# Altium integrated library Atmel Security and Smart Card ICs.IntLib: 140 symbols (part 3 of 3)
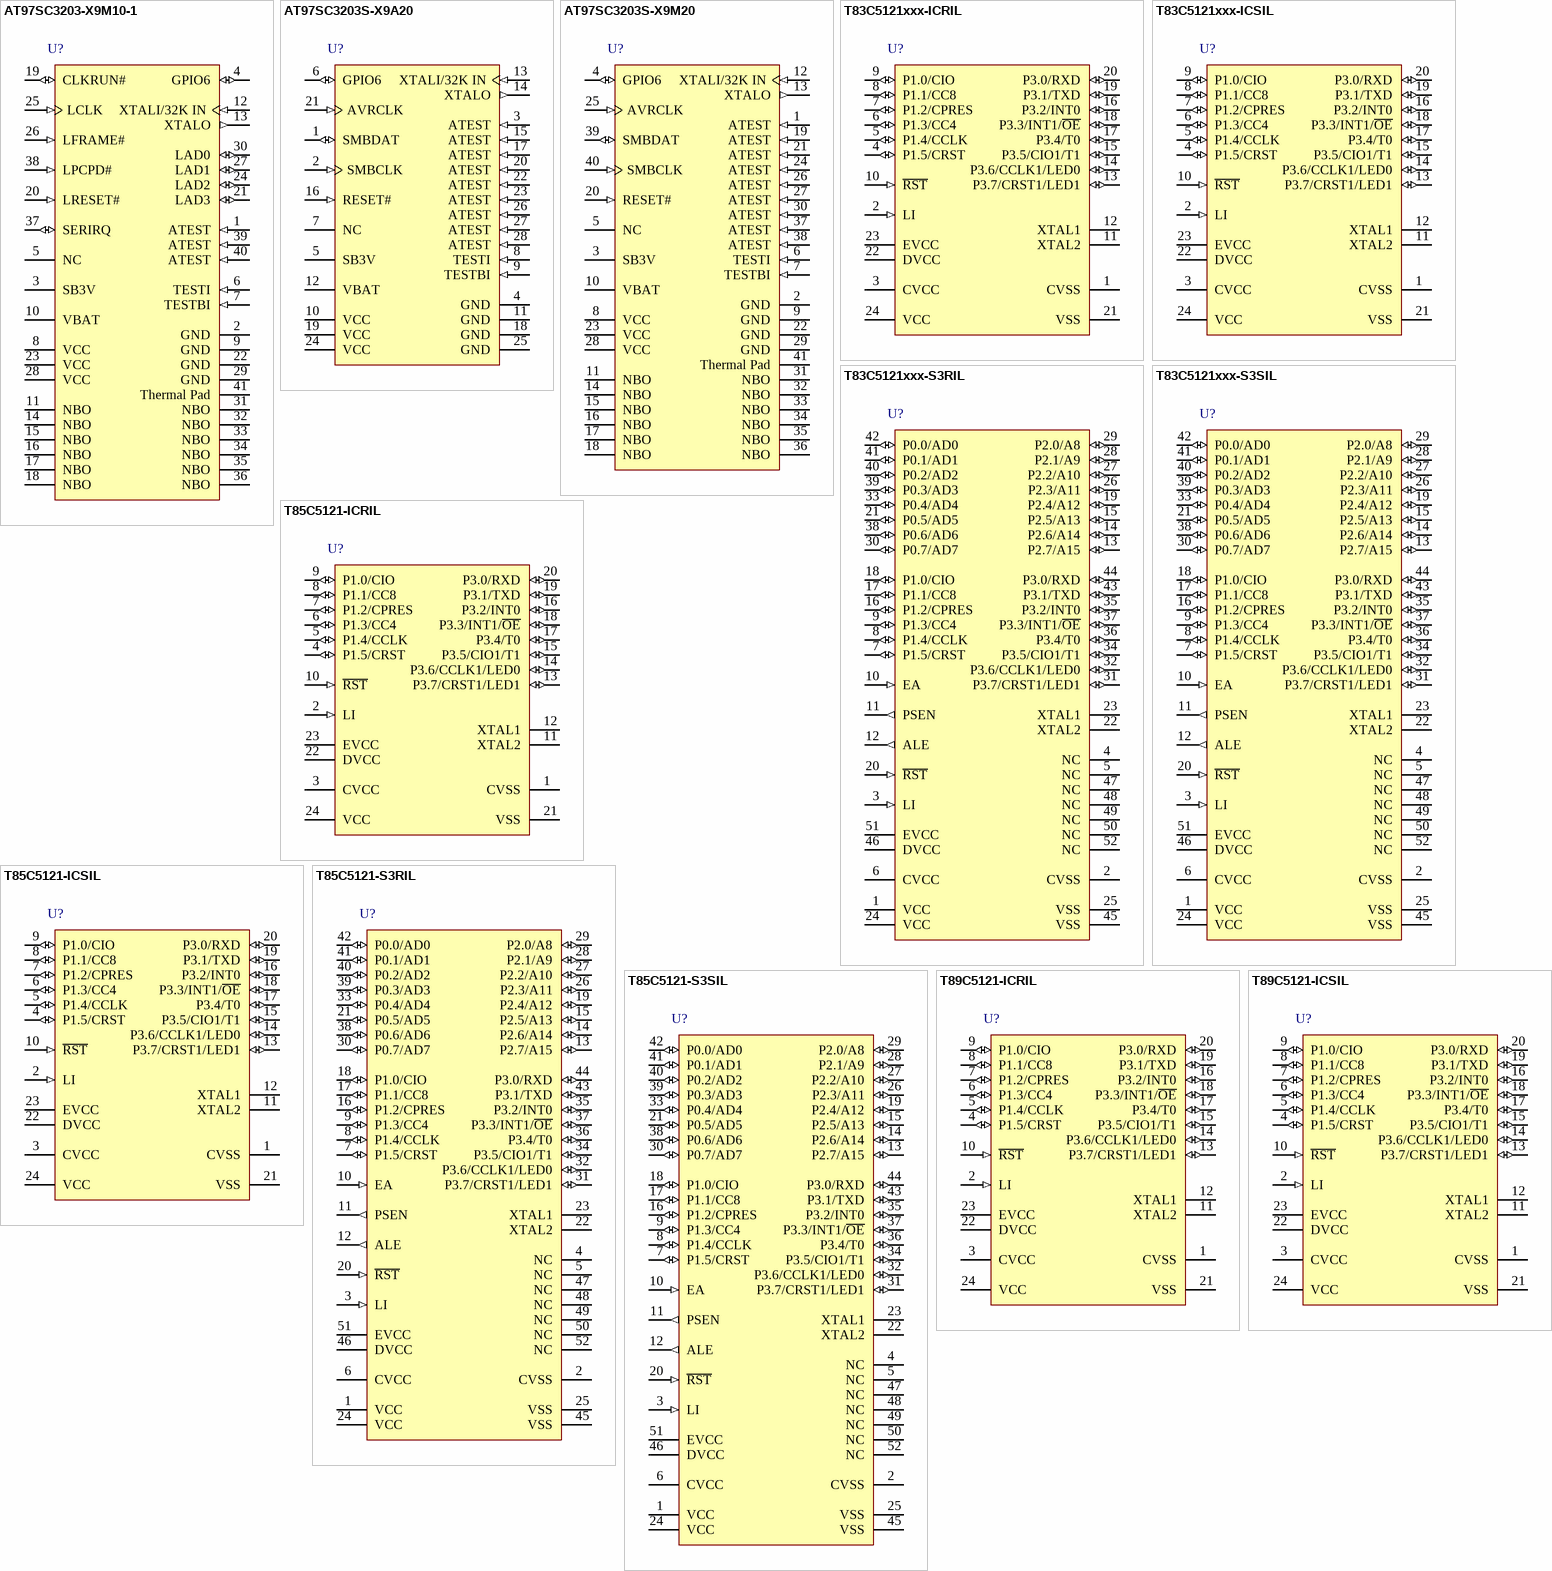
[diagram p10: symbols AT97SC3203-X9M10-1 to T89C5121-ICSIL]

## AT97SC3203S-X9A20
designator U?
Trusted Platform Module, SMBus Two-Wire Interface, Commercial (0 to 70 deg C), 28-Pin TSSOP, Pb-Free
footprint 28A3_N (TSOP, 28-Leads, Body 9.7x6.1mm, Pitch 0.65mm, IPC Medium Density)
footprint 28A3_L (TSOP, 28-Leads, Body 9.7x6.1mm, Pitch 0.65mm, IPC High Density)
footprint 28A3_M (TSOP, 28-Leads, Body 9.7x6.1mm, Pitch 0.65mm, IPC Low Density)
pins: 1 SMBDAT (io), 2 SMBCLK (in), 3 ATEST (in), 4 GND (power), 5 SB3V (power), 6 GPIO6 (io), 7 NC, 8 TESTI (in), 9 TESTBI (in), 10 VCC (power), 11 GND (power), 12 VBAT (power), 13 XTALI/32K IN (in), 14 XTALO (out), 15 ATEST (in), 16 RESET# (in), 17 ATEST (in), 18 GND (power), 19 VCC (power), 20 ATEST (in), 21 AVRCLK (in), 22 ATEST (in), 23 ATEST (in), 24 VCC (power), 25 GND (power), 26 ATEST (in), 27 ATEST (in), 28 ATEST (in)

## AT97SC3203S-X9M20
designator U?
Trusted Platform Module, SMBus Two-Wire Interface, Commercial (0 to 70 deg C), 40-Pin QFN, Pb-Free
footprint 40ML1_N (QFN, 40-Leads, Body 6x6mm, Pitch 0.5mm, IPC Medium Density)
footprint 40ML1_L (QFN, 40-Leads, Body 6x6mm, Pitch 0.5mm, IPC High Density)
footprint 40ML1_M (QFN, 40-Leads, Body 6x6mm, Pitch 0.5mm, IPC Low Density)
pins: 1 ATEST (in), 2 GND (power), 3 SB3V (power), 4 GPIO6 (io), 5 NC, 6 TESTI (in), 7 TESTBI (in), 8 VCC (power), 9 GND (power), 10 VBAT (power), 11 NBO, 12 XTALI/32K IN (in), 13 XTALO (out), 14 NBO, 15 NBO, 16 NBO, 17 NBO, 18 NBO, 19 ATEST (in), 20 RESET# (in), 21 ATEST (in), 22 GND (power), 23 VCC (power), 24 ATEST (in), 25 AVRCLK (in), 26 ATEST (in), 27 ATEST (in), 28 VCC (power), 29 GND (power), 30 ATEST (in), 31 NBO, 32 NBO, 33 NBO, 34 NBO, 35 NBO, 36 NBO, 37 ATEST (in), 38 ATEST (in), 39 SMBDAT (io), 40 SMBCLK (in), 41 Thermal Pad (power)

## T83C5121xxx-ICRIL
designator U?
8-bit Microcontroller with Multiprotocol Smart Card Interface, Industrial, 24-Pin SOIC Pkg, Tape and Reel
footprint SSOP24_N (SOP, 24-Leads, Body 8.2x5.3mm, Pitch 0.65mm, IPC Medium Density)
footprint SSOP24_L (SOP, 24-Leads, Body 8.2x5.3mm, Pitch 0.65mm, IPC High Density)
footprint SSOP24_M (SOP, 24-Leads, Body 8.2x5.3mm, Pitch 0.65mm, IPC Low Density)
pins: 1 CVSS (power), 2 LI (in), 3 CVCC (power), 4 P1.5/CRST (io), 5 P1.4/CCLK (io), 6 P1.3/CC4 (io), 7 P1.2/CPRES (io), 8 P1.1/CC8 (io), 9 P1.0/CIO (io), 10 ~{RST} (in), 11 XTAL2, 12 XTAL1, 13 P3.7/CRST1/LED1 (io), 14 P3.6/CCLK1/LED0 (io), 15 P3.5/CIO1/T1 (io), 16 P3.2/INT0 (io), 17 P3.4/T0 (io), 18 P3.3/INT1/~{OE} (io), 19 P3.1/TXD (io), 20 P3.0/RXD (io), 21 VSS (power), 22 DVCC (power), 23 EVCC (power), 24 VCC (power)

## T83C5121xxx-ICSIL
designator U?
8-bit Microcontroller with Multiprotocol Smart Card Interface, Industrial, 24-Pin SOIC Pkg, Stick
footprint SSOP24_N (SOP, 24-Leads, Body 8.2x5.3mm, Pitch 0.65mm, IPC Medium Density)
footprint SSOP24_L (SOP, 24-Leads, Body 8.2x5.3mm, Pitch 0.65mm, IPC High Density)
footprint SSOP24_M (SOP, 24-Leads, Body 8.2x5.3mm, Pitch 0.65mm, IPC Low Density)
pins: 1 CVSS (power), 2 LI (in), 3 CVCC (power), 4 P1.5/CRST (io), 5 P1.4/CCLK (io), 6 P1.3/CC4 (io), 7 P1.2/CPRES (io), 8 P1.1/CC8 (io), 9 P1.0/CIO (io), 10 ~{RST} (in), 11 XTAL2, 12 XTAL1, 13 P3.7/CRST1/LED1 (io), 14 P3.6/CCLK1/LED0 (io), 15 P3.5/CIO1/T1 (io), 16 P3.2/INT0 (io), 17 P3.4/T0 (io), 18 P3.3/INT1/~{OE} (io), 19 P3.1/TXD (io), 20 P3.0/RXD (io), 21 VSS (power), 22 DVCC (power), 23 EVCC (power), 24 VCC (power)

## T83C5121xxx-S3RIL
designator U?
8-bit Microcontroller with Multiprotocol Smart Card Interface, Industrial, 52-Pin LCC Pkg, Tape and Reel; Note: Contact Atmel for availability
footprint PLCC52_N (Leaded Chip Carrier, 52-Leads, Body 19x19mm, Pitch 1.27mm, IPC Medium Density)
footprint PLCC52_L (Leaded Chip Carrier, 52-Leads, Body 19x19mm, Pitch 1.27mm, IPC High Density)
footprint PLCC52_M (Leaded Chip Carrier, 52-Leads, Body 19x19mm, Pitch 1.27mm, IPC Low Density)
pins: 1 VCC (power), 2 CVSS (power), 3 LI (in), 4 NC, 5 NC, 6 CVCC (power), 7 P1.5/CRST (io), 8 P1.4/CCLK (io), 9 P1.3/CC4 (io), 10 EA (in), 11 PSEN (out), 12 ALE (out), 13 P2.7/A15 (io), 14 P2.6/A14 (io), 15 P2.5/A13 (io), 16 P1.2/CPRES (io), 17 P1.1/CC8 (io), 18 P1.0/CIO (io), 19 P2.4/A12 (io), 20 ~{RST} (in), 21 P0.5/AD5 (io), 22 XTAL2, 23 XTAL1, 24 VCC (power), 25 VSS (power), 26 P2.3/A11 (io), 27 P2.2/A10 (io), 28 P2.1/A9 (io), 29 P2.0/A8 (io), 30 P0.7/AD7 (io), 31 P3.7/CRST1/LED1 (io), 32 P3.6/CCLK1/LED0 (io), 33 P0.4/AD4 (io), 34 P3.5/CIO1/T1 (io), 35 P3.2/INT0 (io), 36 P3.4/T0 (io), 37 P3.3/INT1/~{OE} (io), 38 P0.6/AD6 (io), 39 P0.3/AD3 (io), 40 P0.2/AD2 (io), 41 P0.1/AD1 (io), 42 P0.0/AD0 (io), 43 P3.1/TXD (io), 44 P3.0/RXD (io), 45 VSS (power), 46 DVCC (power), 47 NC, 48 NC, 49 NC, 50 NC, 51 EVCC (power), 52 NC

## T83C5121xxx-S3SIL
designator U?
8-bit Microcontroller with Multiprotocol Smart Card Interface, Industrial, 52-Pin LCC Pkg, Stick; Note: Contact Atmel for availability
footprint PLCC52_N (Leaded Chip Carrier, 52-Leads, Body 19x19mm, Pitch 1.27mm, IPC Medium Density)
footprint PLCC52_L (Leaded Chip Carrier, 52-Leads, Body 19x19mm, Pitch 1.27mm, IPC High Density)
footprint PLCC52_M (Leaded Chip Carrier, 52-Leads, Body 19x19mm, Pitch 1.27mm, IPC Low Density)
pins: 1 VCC (power), 2 CVSS (power), 3 LI (in), 4 NC, 5 NC, 6 CVCC (power), 7 P1.5/CRST (io), 8 P1.4/CCLK (io), 9 P1.3/CC4 (io), 10 EA (in), 11 PSEN (out), 12 ALE (out), 13 P2.7/A15 (io), 14 P2.6/A14 (io), 15 P2.5/A13 (io), 16 P1.2/CPRES (io), 17 P1.1/CC8 (io), 18 P1.0/CIO (io), 19 P2.4/A12 (io), 20 ~{RST} (in), 21 P0.5/AD5 (io), 22 XTAL2, 23 XTAL1, 24 VCC (power), 25 VSS (power), 26 P2.3/A11 (io), 27 P2.2/A10 (io), 28 P2.1/A9 (io), 29 P2.0/A8 (io), 30 P0.7/AD7 (io), 31 P3.7/CRST1/LED1 (io), 32 P3.6/CCLK1/LED0 (io), 33 P0.4/AD4 (io), 34 P3.5/CIO1/T1 (io), 35 P3.2/INT0 (io), 36 P3.4/T0 (io), 37 P3.3/INT1/~{OE} (io), 38 P0.6/AD6 (io), 39 P0.3/AD3 (io), 40 P0.2/AD2 (io), 41 P0.1/AD1 (io), 42 P0.0/AD0 (io), 43 P3.1/TXD (io), 44 P3.0/RXD (io), 45 VSS (power), 46 DVCC (power), 47 NC, 48 NC, 49 NC, 50 NC, 51 EVCC (power), 52 NC

## T85C5121-ICRIL
designator U?
8-bit Microcontroller with Multiprotocol Smart Card Interface, Industrial, 24-Pin SOIC Pkg, Tape and Reel
footprint SSOP24_N (SOP, 24-Leads, Body 8.2x5.3mm, Pitch 0.65mm, IPC Medium Density)
footprint SSOP24_L (SOP, 24-Leads, Body 8.2x5.3mm, Pitch 0.65mm, IPC High Density)
footprint SSOP24_M (SOP, 24-Leads, Body 8.2x5.3mm, Pitch 0.65mm, IPC Low Density)
pins: 1 CVSS (power), 2 LI (in), 3 CVCC (power), 4 P1.5/CRST (io), 5 P1.4/CCLK (io), 6 P1.3/CC4 (io), 7 P1.2/CPRES (io), 8 P1.1/CC8 (io), 9 P1.0/CIO (io), 10 ~{RST} (in), 11 XTAL2, 12 XTAL1, 13 P3.7/CRST1/LED1 (io), 14 P3.6/CCLK1/LED0 (io), 15 P3.5/CIO1/T1 (io), 16 P3.2/INT0 (io), 17 P3.4/T0 (io), 18 P3.3/INT1/~{OE} (io), 19 P3.1/TXD (io), 20 P3.0/RXD (io), 21 VSS (power), 22 DVCC (power), 23 EVCC (power), 24 VCC (power)

## T85C5121-ICSIL
designator U?
8-bit Microcontroller with Multiprotocol Smart Card Interface, Industrial, 24-Pin SOIC Pkg, Stick
footprint SSOP24_N (SOP, 24-Leads, Body 8.2x5.3mm, Pitch 0.65mm, IPC Medium Density)
footprint SSOP24_L (SOP, 24-Leads, Body 8.2x5.3mm, Pitch 0.65mm, IPC High Density)
footprint SSOP24_M (SOP, 24-Leads, Body 8.2x5.3mm, Pitch 0.65mm, IPC Low Density)
pins: 1 CVSS (power), 2 LI (in), 3 CVCC (power), 4 P1.5/CRST (io), 5 P1.4/CCLK (io), 6 P1.3/CC4 (io), 7 P1.2/CPRES (io), 8 P1.1/CC8 (io), 9 P1.0/CIO (io), 10 ~{RST} (in), 11 XTAL2, 12 XTAL1, 13 P3.7/CRST1/LED1 (io), 14 P3.6/CCLK1/LED0 (io), 15 P3.5/CIO1/T1 (io), 16 P3.2/INT0 (io), 17 P3.4/T0 (io), 18 P3.3/INT1/~{OE} (io), 19 P3.1/TXD (io), 20 P3.0/RXD (io), 21 VSS (power), 22 DVCC (power), 23 EVCC (power), 24 VCC (power)

## T85C5121-S3RIL
designator U?
8-bit Microcontroller with Multiprotocol Smart Card Interface, Industrial, 52-Pin LCC Pkg, Tape and Reel
footprint PLCC52_N (Leaded Chip Carrier, 52-Leads, Body 19x19mm, Pitch 1.27mm, IPC Medium Density)
footprint PLCC52_L (Leaded Chip Carrier, 52-Leads, Body 19x19mm, Pitch 1.27mm, IPC High Density)
footprint PLCC52_M (Leaded Chip Carrier, 52-Leads, Body 19x19mm, Pitch 1.27mm, IPC Low Density)
pins: 1 VCC (power), 2 CVSS (power), 3 LI (in), 4 NC, 5 NC, 6 CVCC (power), 7 P1.5/CRST (io), 8 P1.4/CCLK (io), 9 P1.3/CC4 (io), 10 EA (in), 11 PSEN (out), 12 ALE (out), 13 P2.7/A15 (io), 14 P2.6/A14 (io), 15 P2.5/A13 (io), 16 P1.2/CPRES (io), 17 P1.1/CC8 (io), 18 P1.0/CIO (io), 19 P2.4/A12 (io), 20 ~{RST} (in), 21 P0.5/AD5 (io), 22 XTAL2, 23 XTAL1, 24 VCC (power), 25 VSS (power), 26 P2.3/A11 (io), 27 P2.2/A10 (io), 28 P2.1/A9 (io), 29 P2.0/A8 (io), 30 P0.7/AD7 (io), 31 P3.7/CRST1/LED1 (io), 32 P3.6/CCLK1/LED0 (io), 33 P0.4/AD4 (io), 34 P3.5/CIO1/T1 (io), 35 P3.2/INT0 (io), 36 P3.4/T0 (io), 37 P3.3/INT1/~{OE} (io), 38 P0.6/AD6 (io), 39 P0.3/AD3 (io), 40 P0.2/AD2 (io), 41 P0.1/AD1 (io), 42 P0.0/AD0 (io), 43 P3.1/TXD (io), 44 P3.0/RXD (io), 45 VSS (power), 46 DVCC (power), 47 NC, 48 NC, 49 NC, 50 NC, 51 EVCC (power), 52 NC

## T85C5121-S3SIL
designator U?
8-bit Microcontroller with Multiprotocol Smart Card Interface, Industrial, 52-Pin LCC Pkg, Stick
footprint PLCC52_N (Leaded Chip Carrier, 52-Leads, Body 19x19mm, Pitch 1.27mm, IPC Medium Density)
footprint PLCC52_L (Leaded Chip Carrier, 52-Leads, Body 19x19mm, Pitch 1.27mm, IPC High Density)
footprint PLCC52_M (Leaded Chip Carrier, 52-Leads, Body 19x19mm, Pitch 1.27mm, IPC Low Density)
pins: 1 VCC (power), 2 CVSS (power), 3 LI (in), 4 NC, 5 NC, 6 CVCC (power), 7 P1.5/CRST (io), 8 P1.4/CCLK (io), 9 P1.3/CC4 (io), 10 EA (in), 11 PSEN (out), 12 ALE (out), 13 P2.7/A15 (io), 14 P2.6/A14 (io), 15 P2.5/A13 (io), 16 P1.2/CPRES (io), 17 P1.1/CC8 (io), 18 P1.0/CIO (io), 19 P2.4/A12 (io), 20 ~{RST} (in), 21 P0.5/AD5 (io), 22 XTAL2, 23 XTAL1, 24 VCC (power), 25 VSS (power), 26 P2.3/A11 (io), 27 P2.2/A10 (io), 28 P2.1/A9 (io), 29 P2.0/A8 (io), 30 P0.7/AD7 (io), 31 P3.7/CRST1/LED1 (io), 32 P3.6/CCLK1/LED0 (io), 33 P0.4/AD4 (io), 34 P3.5/CIO1/T1 (io), 35 P3.2/INT0 (io), 36 P3.4/T0 (io), 37 P3.3/INT1/~{OE} (io), 38 P0.6/AD6 (io), 39 P0.3/AD3 (io), 40 P0.2/AD2 (io), 41 P0.1/AD1 (io), 42 P0.0/AD0 (io), 43 P3.1/TXD (io), 44 P3.0/RXD (io), 45 VSS (power), 46 DVCC (power), 47 NC, 48 NC, 49 NC, 50 NC, 51 EVCC (power), 52 NC

## T89C5121-ICRIL
designator U?
8-bit Microcontroller with Multiprotocol Smart Card Interface, Industrial, 24-Pin SOIC Pkg, Tape and Reel
footprint SSOP24_N (SOP, 24-Leads, Body 8.2x5.3mm, Pitch 0.65mm, IPC Medium Density)
footprint SSOP24_L (SOP, 24-Leads, Body 8.2x5.3mm, Pitch 0.65mm, IPC High Density)
footprint SSOP24_M (SOP, 24-Leads, Body 8.2x5.3mm, Pitch 0.65mm, IPC Low Density)
pins: 1 CVSS (power), 2 LI (in), 3 CVCC (power), 4 P1.5/CRST (io), 5 P1.4/CCLK (io), 6 P1.3/CC4 (io), 7 P1.2/CPRES (io), 8 P1.1/CC8 (io), 9 P1.0/CIO (io), 10 ~{RST} (in), 11 XTAL2, 12 XTAL1, 13 P3.7/CRST1/LED1 (io), 14 P3.6/CCLK1/LED0 (io), 15 P3.5/CIO1/T1 (io), 16 P3.2/INT0 (io), 17 P3.4/T0 (io), 18 P3.3/INT1/~{OE} (io), 19 P3.1/TXD (io), 20 P3.0/RXD (io), 21 VSS (power), 22 DVCC (power), 23 EVCC (power), 24 VCC (power)

## T89C5121-ICSIL
designator U?
8-bit Microcontroller with Multiprotocol Smart Card Interface, Industrial, 24-Pin SOIC Pkg, Stick
footprint SSOP24_N (SOP, 24-Leads, Body 8.2x5.3mm, Pitch 0.65mm, IPC Medium Density)
footprint SSOP24_L (SOP, 24-Leads, Body 8.2x5.3mm, Pitch 0.65mm, IPC High Density)
footprint SSOP24_M (SOP, 24-Leads, Body 8.2x5.3mm, Pitch 0.65mm, IPC Low Density)
pins: 1 CVSS (power), 2 LI (in), 3 CVCC (power), 4 P1.5/CRST (io), 5 P1.4/CCLK (io), 6 P1.3/CC4 (io), 7 P1.2/CPRES (io), 8 P1.1/CC8 (io), 9 P1.0/CIO (io), 10 ~{RST} (in), 11 XTAL2, 12 XTAL1, 13 P3.7/CRST1/LED1 (io), 14 P3.6/CCLK1/LED0 (io), 15 P3.5/CIO1/T1 (io), 16 P3.2/INT0 (io), 17 P3.4/T0 (io), 18 P3.3/INT1/~{OE} (io), 19 P3.1/TXD (io), 20 P3.0/RXD (io), 21 VSS (power), 22 DVCC (power), 23 EVCC (power), 24 VCC (power)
